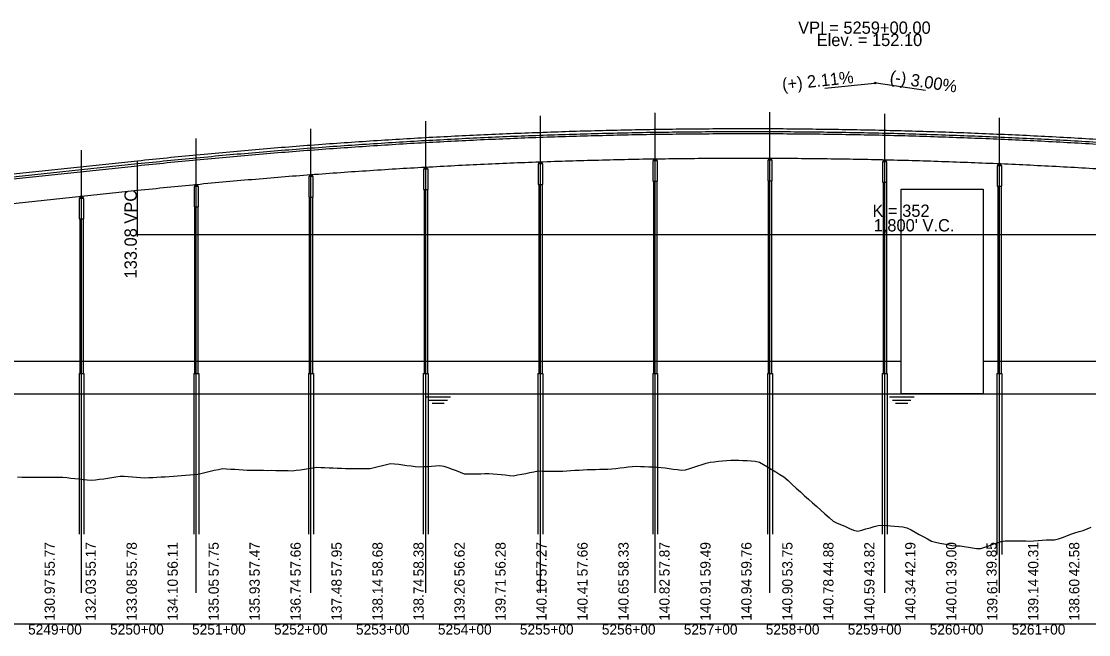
# Model space of a CAD drawing. Extents: x 2121671 to 2169879, y 557274 to 599957.
# Drawn here: x 2154426 to 2155728, y 579173 to 579923 of the extents above; entities that cross this region are included whole.
import ezdxf

# ---------------------------------------------------------------- set-up
doc = ezdxf.new("R2010")
doc.units = 0
for name, color, linetype in [('BR_CENTER LINES', 7, 'Continuous'), ('BR_CONCRETE', 7, 'Continuous'), ('BR_DETAILS', 7, 'Continuous'), ('BR_PRESTRESSED BEAM', 7, 'Continuous'), ('RD_DDB_GradeTX', 7, 'Continuous'), ('RD_DDB_Profile_Elev', 7, 'Continuous'), ('RD_DDB_Profile_EX', 7, 'Continuous'), ('RD_DDB_Profile_Lbl', 7, 'Continuous'), ('RD_DDB_Profile_PR', 7, 'Continuous'), ('RD_DDB_StaTX', 7, 'Continuous'), ('RD_DDB_StripGrade', 7, 'Continuous'), ('RD_DDB_VCLbl', 7, 'Continuous'), ('RD_GPK_Profile_Cell', 7, 'Continuous')]:
    doc.layers.add(name, color=color, linetype=linetype)

msp = doc.modelspace()

# ---------------------------------------------------------------- linework, layer by layer
at = {"layer": 'BR_CENTER LINES'}
for p, q in [((2155339.4, 579224.3), (2155339.4, 579811.5)), ((2154919.4, 579224.3), (2154919.4, 579800.6)), ((2155059.4, 579224.3), (2155059.4, 579807)), ((2155199.4, 579224.3), (2155199.4, 579810.6)), ((2155479.4, 579224.3), (2155479.4, 579809.5)), ((2155619.4, 579224.3), (2155619.4, 579804.8)), ((2154779.4, 579224.3), (2154779.4, 579791.4)), ((2154639.4, 579224.3), (2154639.4, 579779.4)), ((2154499.4, 579224.3), (2154499.4, 579765))]:
    msp.add_line(p, q, dxfattribs=at)
at = {"layer": 'BR_CONCRETE'}
for p, q in [((2154274.9, 579717.8), (2154567.9, 579748.7)), ((2155057.4, 579723.4), (2155057.4, 579492.4)), ((2155061.4, 579723.4), (2155061.4, 579492.4)), ((2155197.4, 579727.1), (2155197.4, 579492.4)), ((2155201.4, 579727.1), (2155201.4, 579492.4)), ((2155337.4, 579727.9), (2155337.4, 579492.4)), ((2155341.4, 579727.9), (2155341.4, 579492.4)), ((2155477.4, 579726), (2155477.4, 579492.4)), ((2155481.4, 579726), (2155481.4, 579492.4)), ((2155617.4, 579721.2), (2155617.4, 579492.4)), ((2155621.4, 579721.2), (2155621.4, 579492.4)), ((2154777.4, 579707.8), (2154777.4, 579492.4)), ((2154781.4, 579707.8), (2154781.4, 579492.4)), ((2154917.4, 579717), (2154917.4, 579492.4)), ((2154921.4, 579717), (2154921.4, 579492.4)), ((2154637.4, 579695.8), (2154637.4, 579492.4)), ((2154641.4, 579695.8), (2154641.4, 579492.4)), ((2154497.4, 579681.3), (2154497.4, 579492.4)), ((2154501.4, 579681.3), (2154501.4, 579492.4)), ((2154496.4, 579492.4), (2154496.4, 579296.1)), ((2154496.4, 579492.4), (2154502.4, 579492.4)), ((2154502.4, 579492.4), (2154502.4, 579296.1)), ((2154636.4, 579492.4), (2154636.4, 579296.1)), ((2154636.4, 579492.4), (2154642.4, 579492.4)), ((2154642.4, 579492.4), (2154642.4, 579296.1)), ((2154776.4, 579492.4), (2154776.4, 579296.1)), ((2154776.4, 579492.4), (2154782.4, 579492.4)), ((2154782.4, 579492.4), (2154782.4, 579296.1)), ((2154916.4, 579492.4), (2154916.4, 579296.1)), ((2154916.4, 579492.4), (2154922.4, 579492.4)), ((2154922.4, 579492.4), (2154922.4, 579296.1)), ((2155056.4, 579492.4), (2155056.4, 579296.1)), ((2155056.4, 579492.4), (2155062.4, 579492.4)), ((2155062.4, 579492.4), (2155062.4, 579296.1)), ((2155196.4, 579492.4), (2155196.4, 579296.1)), ((2155196.4, 579492.4), (2155202.4, 579492.4)), ((2155202.4, 579492.4), (2155202.4, 579296.1)), ((2155336.4, 579492.4), (2155336.4, 579296.1)), ((2155336.4, 579492.4), (2155342.4, 579492.4)), ((2155342.4, 579492.4), (2155342.4, 579296.1)), ((2155476.4, 579492.4), (2155476.4, 579296.1)), ((2155476.4, 579492.4), (2155482.4, 579492.4)), ((2155482.4, 579492.4), (2155482.4, 579296.1)), ((2155616.4, 579492.4), (2155616.4, 579271.3)), ((2155616.4, 579492.4), (2155622.4, 579492.4)), ((2155622.4, 579492.4), (2155622.4, 579271.3))]:
    msp.add_line(p, q, dxfattribs=at)
for points in [[(2155056.7, 579723.4), (2155062.2, 579723.4), (2155062.2, 579748.4), (2155056.7, 579748.4)], [(2155196.7, 579727.1), (2155202.2, 579727.1), (2155202.2, 579752.1), (2155196.7, 579752.1)], [(2155336.7, 579727.9), (2155342.2, 579727.9), (2155342.2, 579752.9), (2155336.7, 579752.9)], [(2155476.7, 579726), (2155482.2, 579726), (2155482.2, 579751), (2155476.7, 579751)], [(2154916.7, 579717), (2154922.2, 579717), (2154922.2, 579742), (2154916.7, 579742)], [(2155616.7, 579721.2), (2155622.2, 579721.2), (2155622.2, 579746.2), (2155616.7, 579746.2)], [(2154636.7, 579695.8), (2154642.2, 579695.8), (2154642.2, 579720.8), (2154636.7, 579720.8)], [(2154776.7, 579707.8), (2154782.2, 579707.8), (2154782.2, 579732.8), (2154776.7, 579732.8)], [(2154496.7, 579681.3), (2154502.2, 579681.3), (2154502.2, 579706.3), (2154496.7, 579706.3)]]:
    msp.add_lwpolyline(points, close=True, dxfattribs=at)
msp.add_spline([(2154567.9, 579748.7), (2154603.9, 579752.4), (2154639.9, 579755.9), (2154675.9, 579759.3), (2154711.9, 579762.4), (2154747.9, 579765.4), (2154783.9, 579768.2), (2154819.9, 579770.8), (2154855.9, 579773.2), (2154891.9, 579775.5), (2154927.9, 579777.5), (2154963.9, 579779.4), (2154999.9, 579781.1), (2155035.9, 579782.6), (2155071.9, 579783.9), (2155107.9, 579785), (2155143.9, 579786), (2155179.9, 579786.8), (2155215.9, 579787.3), (2155251.9, 579787.7), (2155287.9, 579787.9), (2155323.9, 579788), (2155359.9, 579787.8), (2155395.9, 579787.5), (2155431.9, 579787), (2155467.9, 579786.3), (2155503.9, 579785.4), (2155539.9, 579784.3), (2155575.9, 579783), (2155611.9, 579781.6), (2155647.9, 579780), (2155683.9, 579778.2), (2155719.9, 579776.2), (2155755.9, 579774), (2155791.9, 579771.6), (2155827.9, 579769.1), (2155863.9, 579766.3), (2155899.9, 579763.4), (2155935.9, 579760.3), (2155971.9, 579757), (2156007.9, 579753.6), (2156043.9, 579749.9), (2156079.9, 579746.1), (2156115.9, 579742.1), (2156151.9, 579737.9), (2156187.9, 579733.5), (2156223.9, 579728.9), (2156259.9, 579724.1), (2156295.9, 579719.2), (2156331.9, 579714.1), (2156367.9, 579708.8)], degree=3, dxfattribs=at)
at = {"layer": 'BR_DETAILS'}
for points in [[(2155057.9, 579750.9), (2155058.9, 579750.9), (2155058.9, 579748.4), (2155057.9, 579748.4)], [(2155059.9, 579750.9), (2155060.9, 579750.9), (2155060.9, 579748.4), (2155059.9, 579748.4)], [(2155197.9, 579754.6), (2155198.9, 579754.6), (2155198.9, 579752.1), (2155197.9, 579752.1)], [(2155199.9, 579754.6), (2155200.9, 579754.6), (2155200.9, 579752.1), (2155199.9, 579752.1)], [(2155337.9, 579755.4), (2155338.9, 579755.4), (2155338.9, 579752.9), (2155337.9, 579752.9)], [(2155339.9, 579755.4), (2155340.9, 579755.4), (2155340.9, 579752.9), (2155339.9, 579752.9)], [(2155477.9, 579753.5), (2155478.9, 579753.5), (2155478.9, 579751), (2155477.9, 579751)], [(2155479.9, 579753.5), (2155480.9, 579753.5), (2155480.9, 579751), (2155479.9, 579751)], [(2155617.9, 579748.7), (2155618.9, 579748.7), (2155618.9, 579746.2), (2155617.9, 579746.2)], [(2155619.9, 579748.7), (2155620.9, 579748.7), (2155620.9, 579746.2), (2155619.9, 579746.2)], [(2154777.9, 579735.3), (2154778.9, 579735.3), (2154778.9, 579732.8), (2154777.9, 579732.8)], [(2154779.9, 579735.3), (2154780.9, 579735.3), (2154780.9, 579732.8), (2154779.9, 579732.8)], [(2154917.9, 579744.5), (2154918.9, 579744.5), (2154918.9, 579742), (2154917.9, 579742)], [(2154919.9, 579744.5), (2154920.9, 579744.5), (2154920.9, 579742), (2154919.9, 579742)], [(2154637.9, 579723.3), (2154638.9, 579723.3), (2154638.9, 579720.8), (2154637.9, 579720.8)], [(2154639.9, 579723.3), (2154640.9, 579723.3), (2154640.9, 579720.8), (2154639.9, 579720.8)], [(2154497.9, 579708.8), (2154498.9, 579708.8), (2154498.9, 579706.3), (2154497.9, 579706.3)], [(2154499.9, 579708.8), (2154500.9, 579708.8), (2154500.9, 579706.3), (2154499.9, 579706.3)]]:
    msp.add_lwpolyline(points, close=True, dxfattribs=at)
at = {"layer": 'BR_PRESTRESSED BEAM'}
for p, q in [((2154274.9, 579715.3), (2154567.9, 579746.2)), ((2154359.4, 579694.2), (2154567.9, 579716.2))]:
    msp.add_line(p, q, dxfattribs=at)
for points in [[(2154567.9, 579746.2), (2154603.9, 579749.9), (2154639.9, 579753.4), (2154675.9, 579756.8), (2154711.9, 579759.9), (2154747.9, 579762.9), (2154783.9, 579765.7), (2154819.9, 579768.3), (2154855.9, 579770.7), (2154891.9, 579773), (2154927.9, 579775), (2154963.9, 579776.9), (2154999.9, 579778.6), (2155035.9, 579780.1), (2155071.9, 579781.4), (2155107.9, 579782.5), (2155143.9, 579783.5), (2155179.9, 579784.3), (2155215.9, 579784.8), (2155251.9, 579785.2), (2155287.9, 579785.4), (2155323.9, 579785.5), (2155359.9, 579785.3), (2155395.9, 579785), (2155431.9, 579784.5), (2155467.9, 579783.8), (2155503.9, 579782.9), (2155539.9, 579781.8), (2155575.9, 579780.5), (2155611.9, 579779.1), (2155647.9, 579777.5), (2155683.9, 579775.7), (2155719.9, 579773.7), (2155755.9, 579771.5), (2155791.9, 579769.1), (2155827.9, 579766.6), (2155863.9, 579763.8), (2155899.9, 579760.9), (2155935.9, 579757.8), (2155971.9, 579754.5), (2156007.9, 579751.1), (2156043.9, 579747.4), (2156079.9, 579743.6), (2156115.9, 579739.6), (2156151.9, 579735.4), (2156187.9, 579731), (2156223.9, 579726.4), (2156259.9, 579721.6), (2156295.9, 579716.7), (2156331.9, 579711.6), (2156367.9, 579706.3)], [(2154567.9, 579716.2), (2154603.9, 579719.9), (2154639.9, 579723.4), (2154675.9, 579726.8), (2154711.9, 579729.9), (2154747.9, 579732.9), (2154783.9, 579735.7), (2154819.9, 579738.3), (2154855.9, 579740.7), (2154891.9, 579743), (2154927.9, 579745), (2154963.9, 579746.9), (2154999.9, 579748.6), (2155035.9, 579750.1), (2155071.9, 579751.4), (2155107.9, 579752.5), (2155143.9, 579753.5), (2155179.9, 579754.3), (2155215.9, 579754.8), (2155251.9, 579755.2), (2155287.9, 579755.4), (2155323.9, 579755.5), (2155359.9, 579755.3), (2155395.9, 579755), (2155431.9, 579754.5), (2155467.9, 579753.8), (2155503.9, 579752.9), (2155539.9, 579751.8), (2155575.9, 579750.5), (2155611.9, 579749.1), (2155647.9, 579747.5), (2155683.9, 579745.7), (2155719.9, 579743.7), (2155755.9, 579741.5), (2155791.9, 579739.1), (2155827.9, 579736.6), (2155863.9, 579733.8), (2155899.9, 579730.9), (2155935.9, 579727.8), (2155971.9, 579724.5), (2156007.9, 579721.1), (2156043.9, 579717.4), (2156079.9, 579713.6), (2156115.9, 579709.6), (2156151.9, 579705.4), (2156187.9, 579701), (2156223.9, 579696.4), (2156259.9, 579691.6), (2156295.9, 579686.7), (2156331.9, 579681.6), (2156367.9, 579676.3)]]:
    msp.add_spline(points, degree=3, dxfattribs=at)
at = {"layer": 'RD_DDB_GradeTX'}
for p, q in [((2155406.3, 579840.8), (2155466.9, 579847.2)), ((2155529.2, 579838.1), (2155468.9, 579847.2))]:
    msp.add_line(p, q, dxfattribs=at)
msp.add_circle((2155467.9, 579847.3), 1, dxfattribs=at)
at = {"layer": 'RD_DDB_Profile_Elev'}
for p, q in [((2151922.4, 579507.4), (2155499.4, 579507.4)), ((2155599.4, 579507.4), (2156363.2, 579507.4)), ((2151953.5, 579467.4), (2156316.6, 579467.4)), ((2154919.6, 579463.7), (2154949.6, 579463.7)), ((2154923.4, 579459.9), (2154945.9, 579459.9)), ((2155485.2, 579463.7), (2155515.2, 579463.7)), ((2155488.9, 579459.9), (2155511.4, 579459.9)), ((2154927.1, 579456.2), (2154942.1, 579456.2)), ((2155492.7, 579456.2), (2155507.7, 579456.2))]:
    msp.add_line(p, q, dxfattribs=at)
msp.add_lwpolyline([(2155499.4, 579717.4), (2155599.4, 579717.4), (2155599.4, 579467.4), (2155499.4, 579467.4)], close=True, dxfattribs=at)
at = {"layer": 'RD_DDB_Profile_EX'}
for points in [[(2154721.5, 579374.1), (2154726.5, 579374), (2154731.5, 579374.1), (2154736.5, 579374), (2154741.5, 579373.9), (2154746.5, 579373.8), (2154751.5, 579373.7), (2154756.5, 579373.6), (2154761.5, 579374.1), (2154766.5, 579374.9), (2154771.5, 579375.7), (2154776.5, 579376.5), (2154781.5, 579377.3), (2154786.5, 579378), (2154791.5, 579377.7), (2154796.5, 579377.5), (2154801.5, 579377.2), (2154806.5, 579377), (2154811.5, 579376.8), (2154816.5, 579376.6), (2154821.5, 579376.5), (2154826.5, 579376.5), (2154831.5, 579376.4), (2154836.5, 579376.3), (2154841.5, 579376.3), (2154846.5, 579376.2), (2154851.5, 579376.3), (2154856.5, 579377.5), (2154861.5, 579378.7), (2154866.5, 579379.9), (2154871.5, 579381.1), (2154876.5, 579382.3), (2154881.5, 579382.2), (2154886.5, 579381.5), (2154891.5, 579380.8), (2154896.5, 579380.2), (2154901.5, 579379.5), (2154906.5, 579378.8), (2154911.5, 579378.3), (2154916.5, 579378.6), (2154921.5, 579378.9), (2154926.5, 579379.2), (2154931.5, 579379.5), (2154936.5, 579379.8), (2154941.5, 579379.2), (2154946.5, 579377.4), (2154951.5, 579375.5), (2154956.5, 579373.7), (2154961.5, 579371.8), (2154966.5, 579370), (2154971.5, 579369.8), (2154976.5, 579369.9), (2154981.5, 579370), (2154986.5, 579370), (2154991.5, 579370.1), (2154996.5, 579370.2), (2155001.5, 579369.9), (2155006.5, 579369.4), (2155011.5, 579368.9), (2155016.5, 579368.4), (2155021.5, 579367.8), (2155026.5, 579367.5), (2155031.5, 579368.5), (2155036.5, 579369.4), (2155041.5, 579370.4), (2155046.5, 579371.4), (2155051.5, 579372.3), (2155056.5, 579373.3), (2155061.5, 579373.2), (2155066.5, 579373.2), (2155071.5, 579373.1), (2155076.5, 579373.1), (2155081.5, 579373), (2155086.5, 579373.1), (2155091.5, 579373.4), (2155096.5, 579373.7), (2155101.5, 579374.1), (2155106.5, 579374.5), (2155111.5, 579374.8), (2155116.5, 579375.1), (2155121.5, 579375.2), (2155126.5, 579375.3), (2155131.5, 579375.4), (2155136.5, 579375.5), (2155141.5, 579375.6), (2155146.5, 579375.9), (2155151.5, 579376.5), (2155156.5, 579377.1), (2155161.5, 579377.7), (2155166.5, 579378.3), (2155171.5, 579378.9), (2155176.5, 579379.1), (2155181.5, 579378.9), (2155186.5, 579378.7), (2155191.5, 579378.5), (2155196.5, 579378.2), (2155201.5, 579378), (2155206.5, 579377.7), (2155211.5, 579377.1), (2155216.5, 579376.4), (2155221.5, 579375.7)], [(2155221.5, 579375.7), (2155226.5, 579375), (2155231.5, 579374.3), (2155236.5, 579374.6), (2155241.5, 579376.2), (2155246.5, 579377.9), (2155251.5, 579379.6), (2155256.5, 579381.2), (2155261.5, 579382.9), (2155266.5, 579384.1), (2155271.5, 579384.6), (2155276.5, 579385.1), (2155281.5, 579385.6), (2155286.5, 579386.1), (2155291.5, 579386.6), (2155296.5, 579386.7), (2155301.5, 579386.5), (2155306.5, 579386.2), (2155311.5, 579386), (2155316.5, 579385.7), (2155321.5, 579385.4), (2155326.5, 579384.2), (2155331.5, 579381.2), (2155336.5, 579378.2), (2155341.5, 579375.2), (2155346.5, 579372.2), (2155351.5, 579369.2), (2155356.5, 579366.1), (2155361.5, 579361.5), (2155366.5, 579356.9), (2155371.5, 579352.3), (2155376.5, 579347.7), (2155381.5, 579343.1), (2155386.5, 579338.7), (2155391.5, 579334.3), (2155396.5, 579329.8), (2155401.5, 579325.3), (2155406.5, 579320.8), (2155411.5, 579316.3), (2155416.5, 579311.9), (2155421.5, 579309.7), (2155426.5, 579307.6), (2155431.5, 579305.4), (2155436.5, 579303.2), (2155441.5, 579301.1), (2155446.5, 579299.6), (2155451.5, 579301.1), (2155456.5, 579302.6), (2155461.5, 579304), (2155466.5, 579305.5), (2155471.5, 579306.9), (2155476.5, 579307.2), (2155481.5, 579306.8), (2155486.5, 579306.3), (2155491.5, 579305.9), (2155496.5, 579305.4), (2155501.5, 579304.9), (2155506.5, 579304), (2155511.5, 579301.3), (2155516.5, 579298.6), (2155521.5, 579295.9), (2155526.5, 579293.1), (2155531.5, 579290.4), (2155536.5, 579287.5), (2155541.5, 579286.4), (2155546.5, 579285.3), (2155551.5, 579284.3), (2155556.5, 579283.3), (2155561.5, 579282.3), (2155566.5, 579281.9), (2155571.5, 579281.7), (2155576.5, 579280.9), (2155581.5, 579280.2), (2155586.5, 579279.4), (2155591.5, 579278.6), (2155596.5, 579278.5), (2155601.5, 579280.2), (2155606.5, 579282), (2155611.5, 579283.8), (2155616.5, 579285.6), (2155621.5, 579287.3), (2155626.5, 579287.9), (2155631.5, 579287.9), (2155636.5, 579287.9), (2155641.5, 579287.9), (2155646.5, 579287.9), (2155651.5, 579287.9), (2155656.5, 579287.6), (2155661.5, 579287.9), (2155666.5, 579288.3), (2155671.5, 579288.6), (2155676.5, 579289), (2155681.5, 579289.3), (2155686.5, 579289.1), (2155691.5, 579290.3), (2155696.5, 579292.2), (2155701.5, 579294.1), (2155706.5, 579296), (2155711.5, 579297.9), (2155716.5, 579299.3), (2155721.5, 579300.8)], [(2154421.5, 579366), (2154426.5, 579365.9), (2154431.5, 579365.8), (2154436.5, 579365.8), (2154441.5, 579365.7), (2154446.5, 579365.7), (2154451.5, 579365.7), (2154456.5, 579365.7), (2154461.5, 579365.7), (2154466.5, 579365.7), (2154471.5, 579365.7), (2154476.5, 579365.7), (2154481.5, 579365.2), (2154486.5, 579364.7), (2154491.5, 579364.2), (2154496.5, 579363.7), (2154501.5, 579363.1), (2154506.5, 579362.6), (2154511.5, 579362.1), (2154516.5, 579362.5), (2154521.5, 579363.2), (2154526.5, 579363.9), (2154531.5, 579364.7), (2154536.5, 579365.4), (2154541.5, 579366.1), (2154546.5, 579366.8), (2154551.5, 579366.9), (2154556.5, 579366.6), (2154561.5, 579366.2), (2154566.5, 579365.8), (2154571.5, 579365.5), (2154576.5, 579365.1), (2154581.5, 579365.2), (2154586.5, 579365.5), (2154591.5, 579365.8), (2154596.5, 579366), (2154601.5, 579366.3), (2154606.5, 579366.6), (2154611.5, 579366.9), (2154616.5, 579367.3), (2154621.5, 579367.7), (2154626.5, 579368.2), (2154631.5, 579368.6), (2154636.5, 579369.1), (2154641.5, 579369.5), (2154646.5, 579370.6), (2154651.5, 579371.8), (2154656.5, 579372.9), (2154661.5, 579374.1), (2154666.5, 579375.3), (2154671.5, 579376.3), (2154676.5, 579376), (2154681.5, 579375.7), (2154686.5, 579375.4), (2154691.5, 579375), (2154696.5, 579374.7), (2154701.5, 579374.5), (2154706.5, 579374.4), (2154711.5, 579374.3), (2154716.5, 579374.2), (2154721.5, 579374.1)], [(2155721.5, 579300.8), (2155726.5, 579302.8), (2155731.5, 579304.7)]]:
    msp.add_lwpolyline(points, dxfattribs=at)
at = {"layer": 'RD_DDB_Profile_PR'}
msp.add_line((2154274.9, 579721.3), (2154567.9, 579752.2), dxfattribs=at)
msp.add_spline([(2154567.9, 579752.2), (2154603.9, 579756), (2154639.9, 579759.5), (2154675.9, 579762.8), (2154711.9, 579766), (2154747.9, 579769), (2154783.9, 579771.8), (2154819.9, 579774.4), (2154855.9, 579776.8), (2154891.9, 579779), (2154927.9, 579781.1), (2154963.9, 579782.9), (2154999.9, 579784.6), (2155035.9, 579786.1), (2155071.9, 579787.4), (2155107.9, 579788.6), (2155143.9, 579789.5), (2155179.9, 579790.3), (2155215.9, 579790.9), (2155251.9, 579791.3), (2155287.9, 579791.5), (2155323.9, 579791.5), (2155359.9, 579791.4), (2155395.9, 579791), (2155431.9, 579790.5), (2155467.9, 579789.8), (2155503.9, 579788.9), (2155539.9, 579787.8), (2155575.9, 579786.6), (2155611.9, 579785.1), (2155647.9, 579783.5), (2155683.9, 579781.7), (2155719.9, 579779.7), (2155755.9, 579777.5), (2155791.9, 579775.2), (2155827.9, 579772.6), (2155863.9, 579769.9), (2155899.9, 579767), (2155935.9, 579763.9), (2155971.9, 579760.6), (2156007.9, 579757.1), (2156043.9, 579753.5), (2156079.9, 579749.6), (2156115.9, 579745.6), (2156151.9, 579741.4), (2156187.9, 579737), (2156223.9, 579732.4), (2156259.9, 579727.7), (2156295.9, 579722.7), (2156331.9, 579717.6), (2156367.9, 579712.3)], degree=3, dxfattribs=at)
at = {"layer": 'RD_DDB_VCLbl'}
for p, q in [((2154567.9, 579659.8), (2154567.9, 579752.2)), ((2154567.9, 579662.3), (2156367.9, 579662.3))]:
    msp.add_line(p, q, dxfattribs=at)
at = {"layer": 'RD_GPK_Profile_Cell'}
msp.add_line((2151067.9, 579186.8), (2157367.9, 579186.8), dxfattribs=at)

# ---------------------------------------------------------------- texts
at = {"layer": 'RD_DDB_GradeTX'}
for s, rotation, p in [('(+) 2.11%', 6.0299, (2155355, 579838)), ('(-) 3.00%', 351.4692, (2155484.9, 579847.7))]:
    msp.add_text(s, height=15, rotation=rotation, dxfattribs=at).set_placement(p)
at = {"layer": 'RD_DDB_Profile_Lbl'}
for s, p in [('VPI = 5259+00.00', (2155373.8, 579907.3)), ('Elev. = 152.10', (2155396.4, 579892.3))]:
    msp.add_text(s, height=15, dxfattribs=at).set_placement(p)
at = {"layer": 'RD_DDB_StaTX'}
for s, p in [('5249+00', (2154434.3, 579173.5)), ('5250+00', (2154534.3, 579173.5)), ('5251+00', (2154634.3, 579173.5)), ('5252+00', (2154734.3, 579173.5)), ('5253+00', (2154834.3, 579173.5)), ('5254+00', (2154934.3, 579173.5)), ('5255+00', (2155034.3, 579173.5)), ('5256+00', (2155134.3, 579173.5)), ('5257+00', (2155234.3, 579173.5)), ('5258+00', (2155334.3, 579173.5)), ('5259+00', (2155434.3, 579173.5)), ('5260+00', (2155534.3, 579173.5)), ('5261+00', (2155634.3, 579173.5))]:
    msp.add_text(s, height=12.5, dxfattribs=at).set_placement(p)
at = {"layer": 'RD_DDB_StripGrade'}
for s, height, p in [('133.08 VPC', 15, (2154566.9, 579608.5)), ('55.77', 12.5, (2154466.9, 579244.6)), ('55.17', 12.5, (2154516.9, 579244.6)), ('55.78', 12.5, (2154566.9, 579244.6)), ('56.11', 12.5, (2154616.9, 579244.6)), ('57.75', 12.5, (2154666.9, 579244.6)), ('57.47', 12.5, (2154716.9, 579244.6)), ('57.66', 12.5, (2154766.9, 579244.6)), ('57.95', 12.5, (2154816.9, 579244.6)), ('58.68', 12.5, (2154866.9, 579244.6)), ('58.38', 12.5, (2154916.9, 579244.6)), ('56.62', 12.5, (2154966.9, 579244.6)), ('56.28', 12.5, (2155016.9, 579244.6)), ('57.27', 12.5, (2155066.9, 579244.6)), ('57.66', 12.5, (2155116.9, 579244.6)), ('58.33', 12.5, (2155166.9, 579244.6)), ('57.87', 12.5, (2155216.9, 579244.6)), ('59.49', 12.5, (2155266.9, 579244.6)), ('59.76', 12.5, (2155316.9, 579244.6)), ('53.75', 12.5, (2155366.9, 579244.6)), ('44.88', 12.5, (2155416.9, 579244.6)), ('43.82', 12.5, (2155466.9, 579244.6)), ('42.19', 12.5, (2155516.9, 579244.6)), ('39.00', 12.5, (2155566.9, 579244.6)), ('39.85', 12.5, (2155616, 579244.6)), ('40.31', 12.5, (2155666.9, 579244.6)), ('42.58', 12.5, (2155716.9, 579244.6)), ('130.97', 12.5, (2154466.9, 579190.3)), ('132.03', 12.5, (2154516.9, 579190.3)), ('133.08', 12.5, (2154566.9, 579190.3)), ('134.10', 12.5, (2154616.9, 579190.3)), ('135.05', 12.5, (2154666.9, 579190.3)), ('135.93', 12.5, (2154716.9, 579190.3)), ('136.74', 12.5, (2154766.9, 579190.3)), ('137.48', 12.5, (2154816.9, 579190.3)), ('138.14', 12.5, (2154866.9, 579190.3)), ('138.74', 12.5, (2154916.9, 579190.3)), ('139.26', 12.5, (2154966.9, 579190.3)), ('139.71', 12.5, (2155016.9, 579190.3)), ('140.10', 12.5, (2155066.9, 579190.3)), ('140.41', 12.5, (2155116.9, 579190.3)), ('140.65', 12.5, (2155166.9, 579190.3)), ('140.82', 12.5, (2155216.9, 579190.3)), ('140.91', 12.5, (2155266.9, 579190.3)), ('140.94', 12.5, (2155316.9, 579190.3)), ('140.90', 12.5, (2155366.9, 579190.3)), ('140.78', 12.5, (2155416.9, 579190.3)), ('140.59', 12.5, (2155466.9, 579190.3)), ('140.34', 12.5, (2155516.9, 579190.3)), ('140.01', 12.5, (2155566.9, 579190.3)), ('139.61', 12.5, (2155616.9, 579190.3)), ('139.14', 12.5, (2155666.9, 579190.3)), ('138.60', 12.5, (2155716.9, 579190.3))]:
    msp.add_text(s, height=height, rotation=90, dxfattribs=at).set_placement(p)
at = {"layer": 'RD_DDB_VCLbl'}
for s, p in [('K = 352', (2155464.5, 579683.7)), ("1,800' V.C.", (2155465.9, 579665.9))]:
    msp.add_text(s, height=15, dxfattribs=at).set_placement(p)

doc.saveas('drawing.dxf')
